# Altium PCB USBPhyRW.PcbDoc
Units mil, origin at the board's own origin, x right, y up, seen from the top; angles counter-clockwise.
Board outline 2170 x 955 mil, 2 copper layers (Top Layer, Bottom Layer); 39 components, 26 nets, 143 pads, 48 vias.
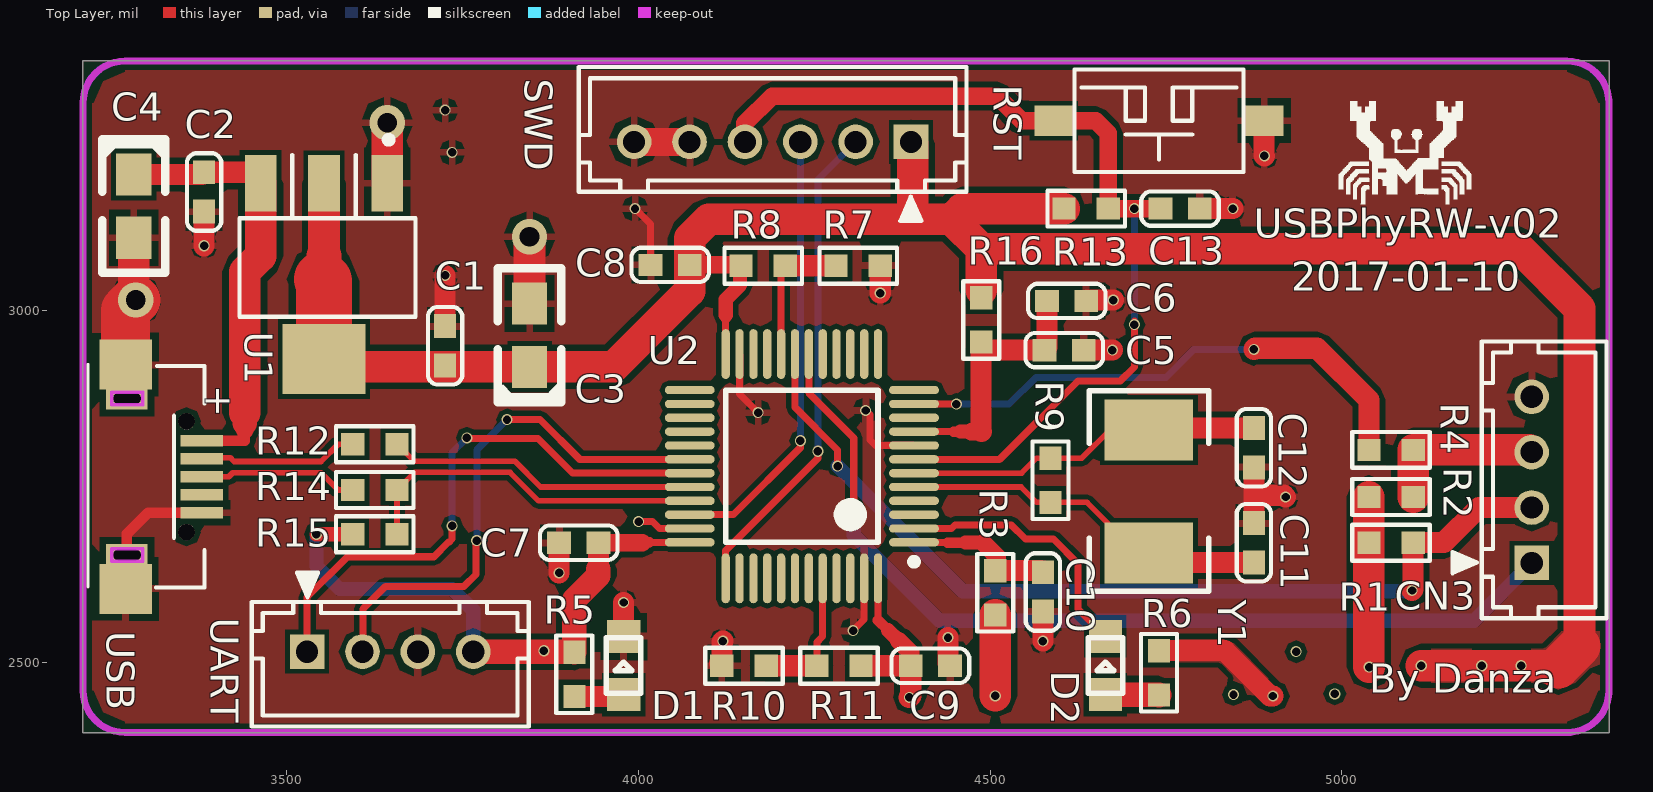
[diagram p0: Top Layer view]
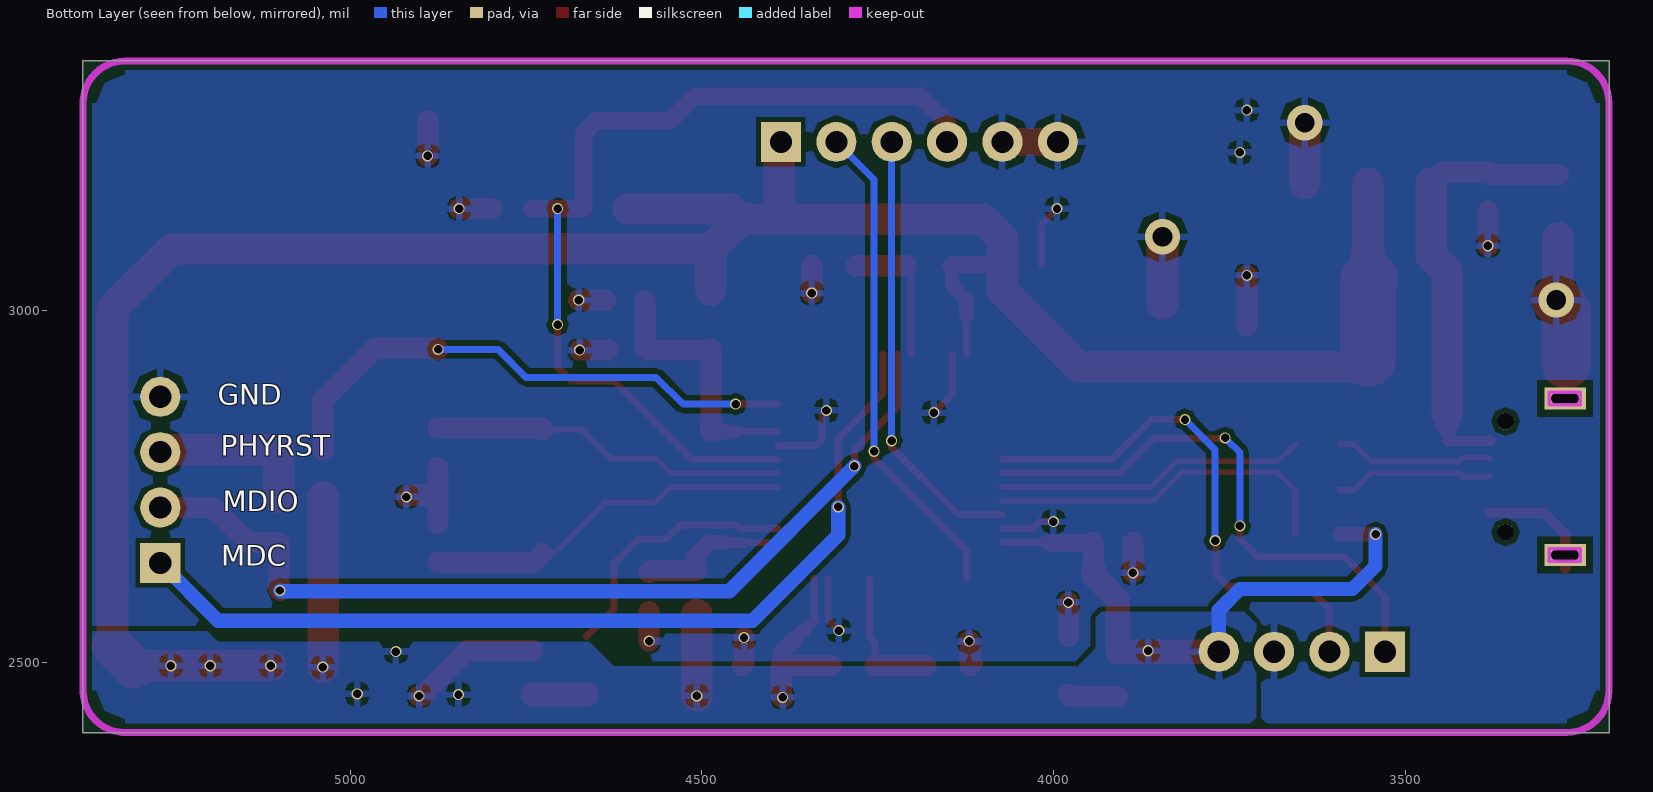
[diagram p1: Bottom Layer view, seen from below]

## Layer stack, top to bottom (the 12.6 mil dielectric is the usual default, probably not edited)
Top Solder: solder mask 0.4, Solder Resist, Dk 3.5
Top Layer: signal copper 1.4
Dielectric 1: dielectric 12.6, FR-4, Dk 4.8
Bottom Layer: signal copper 1.4
Bottom Solder: solder mask 0.4, Solder Resist, Dk 3.5

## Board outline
4045,3355 5380,3355 5380,2420 5380,2410 5380,2400 3210,2400 3210,3345 3210,3355

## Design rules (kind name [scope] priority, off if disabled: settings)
Clearance [All] p1: gap=7
ComponentClearance [All] p1: gap=3 collisioncheckmode=3 verticalgap=7 showdistances=FALSE
DiffPairsRouting [All] p1: maxlimit=8 minlimit=8 mostfreqgap=8 toplayer_minwidth=8 toplayer_maxwidth=30 toplayer_prefwidth=15 bottomlayer_minwidth=8 bottomlayer_maxwidth=30 bottomlayer_prefwidth=15 maxuncoupledlength=500
PolygonConnect [All] p1: connectstyle=Relief reliefconductorwidth=10 reliefentries=4 polygonreliefangle="90 Angle" airgapwidth=10
RoutingVias [All] p1: holewidth=28 width=50 viastyle="Through Hole" minholewidth=10 minwidth=10 maxholewidth=100 maxwidth=100
SilkToSilkClearance [All] p1 off: silktosilkclearance=10
SolderMaskExpansion [All] p1: expansion=4
Width [All] p1: maxlimit=100 minlimit=8 preferedwidth=10 minimp=50.000000 maximp=50.000000 favimp=50.000000
27 further rules are at their usual default settings.

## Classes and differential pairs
component class CoreBoard: C1 C2 C3 C4 C5 C6 C7 C8 C9 C10 C11 C12 C13 CN3 D1 D2 R1 R2 R3 R4 R5 R6 R7 R9 R10 R12 R13 R14 r16 RST SWD U1 UART USB Y1
differential pair USB_1: +NetR12_2 -NetR14_2
differential pair USB_2: +DM_PA11 -DP_PA12
differential pair CLK8M: +OSC_OUT -OSC_IN

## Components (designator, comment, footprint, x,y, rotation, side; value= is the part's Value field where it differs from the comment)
C1 "0.1uf" C0603 3725,2950 r90 top
C2 "0.1uf" C0603 3382.24,3168.74 r270 top
C3 "10uf" SMD-CT-2012 3845,2920 r90 top
C4 "10uf" SMD-CT-2012 3282.24,3193.74 r270 top
C5 "1uf" C0603 4605.2,2943.74 r0 top
C6 "0.1uf" C0603 4608.74,3013.74 r0 top
C7 "0.1uf" C0603 3915,2670 r180 top
C8 "0.1uf" C0603 4045,3065 r180 top
C9 "0.1uf" C0603 4415,2495 r0 top
C10 "0.1uf" C0603 4575,2600 r270 top
C11 "20pF" C0603 4875,2670 r90 top
C12 "20pF" C0603 4875,2805 r90 top
C13 "0.1uf" C0603 4770,3145 r180 top
CN3 "CN_UART" CON_SIP4BOX_2MM 5271.97,2641.26 r90 top
D1 "LED-GREEN" LED-0805 3978.74,2492.76 r270 top
D2 "LED-GREEN" LED-0805 4663.74,2492.76 r270 top
R1 "1.5K/NC" R0603 5070,2670 r180 top
R2 "50k/NC" R0603 5070,2735 r0 top
R3 "0R" R0603 4507.24,2598.74 r270 top
R4 "0R" R0603 5070,2802 r0 top
R5 "1K" R0603 3908.74,2482.76 r270 top
R6 "1K" R0603 4740,2485 r270 top
R7 "10K" R0603 4312.24,3063.82 r180 top
R8 "10K/NC" R0603 4177.24,3063.82 r180 top
R9 "1M" R0603 4585.75,2758.74 r270 top
R10 "10K" R0603 4150,2495 r0 top
R11 "10K/NC" R0603 4285,2495 r0 top
R12 "20R" R0603 3625,2810 r180 top
R13 "10K" R0603 4636.5,3145 r180 top
R14 "20R" R0603 3625,2745 r180 top
R15 "4K7" R0603 3625,2682 r0 top
R16 "0R" R0603 4487.24,2986.74 r270 top (schematic designator L1)
RST "KEYPAD" SWITCH_T06B 4740,3270 r180 top (schematic designator SW1)
SWD "DNP" CON_SIP6BOX_2MM 4387.48,3241.97 r180 top
U1 "LM1117-3.3V" SOT-223 3560,3060 r180 top
U2 "STM32F101C8T6" LQFP48_N 4232.24,2778.74 r180 top
UART "CN_UART" CON_SIP4BOX_2MM 3528.78,2513.03 r0 top (schematic designator CN1)
USB "MICROUSB" MICRO-USB 3292.24,2763.74 r270 top
Y1 "8M" 5032-2P 4725.75,2743.74 r270 top

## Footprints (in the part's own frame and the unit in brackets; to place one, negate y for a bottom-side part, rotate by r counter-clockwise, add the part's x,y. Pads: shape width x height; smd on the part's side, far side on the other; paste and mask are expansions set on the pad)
5032-2P [mm]
  rect 2.2x3.2 smd: 1(-2.2,0) 2(2.25,0)
  silkscreen extent -3.62,-2.16 3.62,2.16
C0603 [mm]
  rect 0.86x0.8 smd: 1(-0.71,0) 2(0.71,0)
  silkscreen extent -1.4,-0.62 1.4,0.62
CON_SIP4BOX_2MM [mm]
  rect 1.25x1.25 / inner rect 1.25x1.25 / far side rect 1.45x1.45 hole 0.8: 1(0,0.05)
  round 1.25 / inner round 1.25 / far side round 1.45 hole 0.8: 2(2,0.05) 3(4,0.05) 4(6,0.05)
  silkscreen extent -2,-2.65 8,2.91
CON_SIP6BOX_2MM [mm]
  rect 1.25x1.25 / inner rect 1.25x1.25 / far side rect 1.45x1.45 hole 0.8: 1(0,0.05)
  round 1.25 / inner round 1.25 / far side round 1.45 hole 0.8: 2(2,0.05) 3(4,0.05) 4(6,0.05) 5(8,0.05) 6(10,0.05)
  silkscreen extent -2,-2.65 12,2.91
LED-0805 [mm]
  rect 1.2x1.2 smd: 1(-1.116,0.003) 2(0.984,0.003)
  silkscreen extent -1.07,-0.62 0.93,0.63
LQFP48_N [mm]
  oval 1.8x0.3 smd: 1(-4.05,2.75) 2(-4.05,2.25) 3(-4.05,1.75) 4(-4.05,1.25) 5(-4.05,0.75) 6(-4.05,0.25) 7(-4.05,-0.25) 8(-4.05,-0.75) 9(-4.05,-1.25) 10(-4.05,-1.75) 11(-4.05,-2.25) 12(-4.05,-2.75) 25(4.05,-2.75) 26(4.05,-2.25) 27(4.05,-1.75) 28(4.05,-1.25) 29(4.05,-0.75) 30(4.05,-0.25) 31(4.05,0.25) 32(4.05,0.75) 33(4.05,1.25) 34(4.05,1.75) 35(4.05,2.25) 36(4.05,2.75)
  oval 0.3x1.8 smd: 13(-2.75,-4.05) 14(-2.25,-4.05) 15(-1.75,-4.05) 16(-1.25,-4.05) 17(-0.75,-4.05) 18(-0.25,-4.05) 19(0.25,-4.05) 20(0.75,-4.05) 21(1.25,-4.05) 22(1.75,-4.05) 23(2.25,-4.05) 24(2.75,-4.05) 37(2.75,4.05) 38(2.25,4.05) 39(1.75,4.05) 40(1.25,4.05) 41(0.75,4.05) 42(0.25,4.05) 43(-0.25,4.05) 44(-0.75,4.05) 45(-1.25,4.05) 46(-1.75,4.05) 47(-2.25,4.05) 48(-2.75,4.05)
  silkscreen extent -4.18,-2.75 2.75,3.57
MICRO-USB [mm]
  rect 0.4x1.55 smd: 1(-1.3,2.2) 2(-0.65,2.2) 3(0,2.2) 4(0.65,2.2) 5(1.3,2.2)
  rect 1.8x1.9 smd: 6(-4.05,-0.55) 6(4.05,-0.55)
  rect 0.8x1.5 hole 0.4 slot 1 at 90 deg: 6(-2.825,-0.5) 6(2.825,-0.5)
  round 0.6 hole 0.6 unplated: ""(-2,1.65) ""(2,1.65)
  Keep-Out Layer lines w0.127: 3.054,-1.043 2.596,-1.043 2.596,0.075 3.054,0.075 3.054,-1.043 ; -2.596,-1.043 -3.054,-1.043 -3.054,0.075 -2.596,0.075 -2.596,-1.043
  silkscreen extent -4.06,-1.91 4,2.3
R0603 [mm]
  rect 0.84x0.8 smd: 1(-0.8,0) 2(0.8,0)
  silkscreen extent -1.4,-0.65 1.4,0.65
SMD-CT-2012 [mil]
  rect 60x50 smd: 1(0,0) 2(90,0)
  silkscreen extent -50,-45 140,45
SOT-223 [mil]
  rect 45x80 smd: 1(-82.76,-121.26) 2(7.24,-121.26) 3(97.24,-121.26)
  rect 118x100 smd: 4(7.24,128.74)
  silkscreen extent -123,-188 127,69
SWITCH_T06B [mm]
  rect 1.4x1.1 smd: 1(-3.8,0) 2(3.8,0)
  silkscreen extent -3.05,-1.85 3.05,1.85

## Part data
C1 C2 C5 C6 C7 C8 C9 C10 C13: library part CAP_1, "Capacitor"
C3 C4: library part CAPACITOR, "Capacitor"
C11 C12: library part CAP, "Capacitor"
CN3 UART: library part CON4
D1 D2: library part LED
R1 R2 R3 R4 R5 R6 R7 R8 R9 R10 R11 R12 R13 R14: library part RES1
R16: library part INDUCTOR1
RST: library part PUSHBUTTON_TSKB-2L_0
SWD: library part CON6
U1: library part LM1117
U2: "STM32 ARM-based 32-bit MCU with 64 Kbytes Flash, 48-pin LQFP, Industrial Temperature"
Y1: library part CRYSTAL, "Crystal"

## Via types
v1: diameter 15.75, hole 12, Top Layer to Bottom Layer, 45 vias
v2: diameter 50, hole 28, Top Layer to Bottom Layer, 3 vias

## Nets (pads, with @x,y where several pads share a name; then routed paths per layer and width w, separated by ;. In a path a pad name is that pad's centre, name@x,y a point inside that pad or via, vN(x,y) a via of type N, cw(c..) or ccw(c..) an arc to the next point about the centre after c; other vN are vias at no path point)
BOOT0: R10.2 R11.1 U2.44 | length 199.7
  Top Layer w10: R11.1 4253.5,2528.5 4261.77,2536.77 U2.44
  Top Layer w30: R10.2 R11.1
BOOT1: R7.2 R8.1 U2.20 | length 200.1
  Top Layer w10: U2.20 4202.72,3057.8 R8.1
  Top Layer w30: R8.1 R7.2
DM_PA11: R12.1 U2.32 | length 441.5
  Top Layer w8: R12.1 3680.5,2786 3824,2786 3860.79,2749.21 U2.32
DP_PA12: R14.1 R15.2 U2.33 | length 506.4
  Top Layer w8: R15.2 R14.1 3681.5,2770 3817.37,2770 3857.84,2729.53 U2.33
GND: C1.2 C2.2 C3.2 C4.2 C5.2 C6.2 C7.2 C8.2 C9.2 C10.2 C11.2 C12.1 C13.1 CN3.4 D1.1 R7.1 R10.1 RST.1 SWD.5 SWD.6 U1.1 U2.8 U2.23 U2.35 U2.47 UART.3 USB.5 USB.6 | length 1742.8
  Top Layer w10: v1(3995,3145) 4017.05,3122.95 C8.2 ; v1(4000,2700) 4020,2700 4029.84,2690.16 U2.35 ; U2.23 4143.66,2881.34 v1(4170,2855) ; v1(4305,2545) 4320.83,2560.83 U2.47 ; v1(4323,2858) 4329,2852 4329,2816 4336.73,2808.27 U2.8
  Top Layer w15: USB.6@3272.56,2633.52 3272.56,2652.52 3272.56,2682.56 3302.56,2712.56 USB.5
  Top Layer w30: v1(3382.24,3092.24) C2.2 ; C1.2 v1(3725,3050) ; v1(3887.05,2627.05) C7.2 ; D1.1 v1(3978.86,2585) ; R10.1@4115,2498.5 R10.1 4118.5,2528.5 v1(4120,2530) ; v1(4343.74,3025) R7.1 ; v1(4440,2535) 4440,2497.95 C9.2 ; v1(4575,2530) C10.2 ; C5.2 v1(4673.74,2943.74) ; C6.2 4637.95,3015 v1(4675,3015) ; C13.1 v1(4845,3145) ; C11.2 4875,2737.5 ; C12.1 4875,2737.5 ; RST.1 4889.61,3220.39 v1(4890,3220) ; v1(4920,2735) 4917.5,2737.5 4875,2737.5
  Top Layer w40: SWD.6 SWD.5
  Top Layer w45: C4.2 3282.24,3017.76 v2(3285,3015) ; U1.1 v2(3642.76,3267.24) ; C3.2 v2(3845,3105)
  Top Layer w70: USB.6@3270.59,2923.19 3270.59,3000.59 v2(3285,3015)
  other v1: 3735,3225 3725,3285
NetD1_2: D1.2 R5.2 | length 71.3
  Top Layer w30: R5.2 3976.1,2451.26 D1.2
NetD2_2: D2.2 R6.2 | length 76.4
  Top Layer w35: D2.2 4739.49,2454.02 R6.2
NetQ1_1: 
NetR12_2: R12.2 USB.2 | length 227.8
  Top Layer w8: USB.2 3380.53,2791 3419.5,2791 3425,2785.5 3548.47,2785.5 3572.97,2810 R12.2
NetR14_2: R14.2 USB.3 | length 229
  Top Layer w8: USB.3@3380.12,2765 USB.3 3417.24,2763.74 3423,2769.5 3548.47,2769.5 3572.97,2745 R14.2
NRST: C13.2 R13.1 RST.2 SWD.4 U2.7 | length 1359.8
  Top Layer w10: U2.7 4513.58,2788.58 4625,2900 4685,2900 4705,2920 v1(4705,2980) v1@4705,2985
  Top Layer w25: SWD.4 4151.26,3266.26 4190,3305 4510,3305 4545,3270 RST.2 4650,3270 4667.99,3252.01 R13.1 v1(4705.02,3145) C13.2
  Bottom Layer w10: v1(4705,2980) v1(4705.02,3145)
OSC_IN: C11.1 R9.2 U2.5 Y1.2 | length 527.7
  Top Layer w8: U2.5 4544.03,2749.21 4566,2727.24 R9.2 4637.76,2727.24 4709.84,2655.16 Y1.2
  Top Layer w30: Y1.2 4738.86,2642.05 C11.1
OSC_OUT: C12.2 R9.1 U2.6 Y1.1 | length 509.8
  Top Layer w8: U2.6 4544.66,2768.9 4566,2790.24 R9.1 4630.24,2790.24 4670.35,2830.35 Y1.1
  Top Layer w30: Y1.1 4728.35,2832.95 C12.2
PC13: D2.1 U2.2 | length 377.5
  Top Layer w10: U2.2 4445.16,2690.16 4450,2695 4530,2695 4550,2675 4590,2675 4625,2640 4625,2575.55 D2.1
PHYRST: R4.1 U2.11 | length 781.5
  Top Layer w10: U2.11 v1@4452.32,2867.32
  Top Layer w30: v1(4875,2945) 4876.5,2946.5 4965,2946.5 5038.5,2872.99 R4.1
  Bottom Layer w10: v1(4452,2867) 4527,2867 4565,2905 4750,2905 4790,2945 v1(4875,2945)
PHYRST#: CN3.3 R2.2 R4.2 | length 241.5
  Top Layer w45: R2.2 R4.2 ; R4.2@5104.76,2798.74 R4.2 ; CN3.3 5266.74,2802 R4.2
RX1: U2.31 UART.1 | length 808.3
  Top Layer w10: UART.1 3528.78,2592.78 3586,2650 3709,2650 3730,2671 3731,2671 3735,2675 v1(3735,2694) ; v1(3756,2819) 3757,2818 3857,2818 3906.1,2768.9 U2.31
  Bottom Layer w10: v1(3735,2694) 3735,2798 v1(3756,2819)
SMIMDC: CN3.1 U2.18 | length 1332.3
  Top Layer w10: U2.18 4242.09,2882.91 4306,2819 v1(4306,2721)
  Bottom Layer w20: v1(4306,2721) 4306,2681 4428,2559 5187.74,2559 CN3.1
SMIMDIO: CN3.2 R1.1 U2.19 | length 1333.3
  Top Layer w10: U2.19 4222.4,2862.6 4283,2802 v1(4283,2779)
  Top Layer w30: v1(5100,2602) 5101.5,2603.5 R1.1 5145,2670 5195,2720 CN3.2
  Bottom Layer w20: v1(4283,2779) 4461,2601 5099,2601 v1(5100,2602)
SWCLK: SWD.2 U2.37 | length 697.2
  Top Layer w10: U2.37 4123.98,2658.98 4255,2790 v1(4255,2800)
  Bottom Layer w10: v1(4255,2800) 4255,3186.26 SWD.2
SWDIO: SWD.3 U2.34 | length 631.6
  Top Layer w10: U2.34 4134.84,2709.84 4230,2805 v1(4230,2815)
  Bottom Layer w10: v1(4230,2815) SWD.3
TX1: U2.30 UART.2 | length 763.9
  Top Layer w10: UART.2 3608,2515.48 3608,2576 3640,2608 3752,2608 3769,2625 3769,2672 v1(3770,2673) ; v1(3813,2845) 3860,2845 3916.42,2788.58 U2.30
  Bottom Layer w10: v1(3770,2673) 3770,2802 v1(3813,2845)
USB_5V: C2.1 C4.1 U1.3 USB.1 | length 625
  Top Layer w15: USB.1 3439.92,2814.92 3439.92,2829.92
  Top Layer w25: 3439.92,2829.92 3439.92,2839.92
  Top Layer w30: C4.1 3379.29,3193.74 C2.1 3447.32,3196.69 U1.3
  Top Layer w35: 3439.92,2839.92 3439.92,2854.92
  Top Layer w45: 3439.92,2854.92 3439.92,2909.92 3440,2910 3440,3055 3462.76,3077.76 U1.3
VBAT: C10.1 R3.1 U2.1 | length 216.4
  Top Layer w10: U2.1 4392.17,2670 4440,2670
  Top Layer w15: 4440,2670 4465,2670
  Top Layer w20: 4465,2670 4490,2670
  Top Layer w25: 4490,2670 4510,2650 4507.24,2647.24 R3.1
  Top Layer w30: R3.1 4572.72,2630.24 C10.1
VCC_3V3: C1.1 C3.1 C7.1 C8.1 C9.1 R1.2 R2.1 R3.2 R5.1 R6.1 R8.2 R11.2 R13.2 R15.1 R16.1 SWD.1 U1.2 U1.4 U2.24 U2.36 U2.48 UART.4 | length 5143.4
  Top Layer w10: 4015.47,2670.47 U2.36 ; U2.24 4123.98,2988.98 ; 4340.51,2560 U2.48
  Top Layer w15: 4005.47,2670.47 4015.47,2670.47 ; 4123.98,2988.98 4123.98,2993.98 ; 4340.51,2560 4355,2545.51
  Top Layer w20: v1(3542,2682) R15.1 ; 4005,2670 4005.47,2670.47 ; 4123.98,2993.98 4123.98,3015.98 4144.57,3036.57 R8.2@4144.57,3065 ; 4355,2545.51 4370,2530.51
  Top Layer w25: C7.1 4005,2670 ; C8.1 4144.57,3065 R8.2 ; 4370,2530.51 4387.05,2513.46 C9.1
  Top Layer w30: 3942.95,2632.05 C7.1 ; R11.2 C9.1 4387.05,2452.05 v1(4385,2450) ; R6.1 4833.5,2516.5 4898,2452 v1(4902,2452)
  Top Layer w35: UART.4 3907.99,2515 R5.1 3908.74,2588.74 3942.95,2622.95 3942.95,2632.05
  Top Layer w45: U1.4 3564.02,2920 C3.1 3965,2920 4072.95,3027.95 C8.1 4072.95,3102.95 4100,3130 4390,3130 ; 3552.76,3077.76 U1.2 ; SWD.1 4390,3237.48 4390,3130 ; R16.1@4487.24,3028.74 4487.24,3087.76 ; v1(4507.24,2452.24) R3.2 ; R13.2 4460,3145 4445,3130 ; R2.1 R1.2 5038.5,2493.5 v1(5039,2493) ; v1(5113,2495) v1(5199,2495) v1(5255,2495) 5306,2495 5308,2493 ; 5338,2523 5338,3003 5253.24,3087.76 4487.24,3087.76 ; 4390,3130 4445,3130 ; 4445,3130 4487.24,3087.76
  Top Layer w50: 3552.76,3047.24 3552.76,3077.76
  Top Layer w55: 3550,3044.49 3552.76,3047.24
  Top Layer w60: 5308,2493 5338,2523
  Top Layer w80: 3550,3044.49 3552.76,3041.73 U1.4
  Bottom Layer w20: v1(3542,2682) 3542,2637 3575,2604 3735,2604 3765,2574 UART.4
  other v1: 4846,2454 4990,2455 4935,2515 3865.4,2516.32
VDDA: C5.1 C6.1 R16.2 U2.9 | length 375.2
  Top Layer w10: U2.9 4447.95,2827.95
  Top Layer w15: 4447.95,2827.95 4457.95,2827.95
  Top Layer w20: 4457.95,2827.95 4472.95,2827.95
  Top Layer w25: 4472.95,2827.95 4487.95,2827.95
  Top Layer w30: 4487.95,2827.95 4487.24,2828.66 4487.24,2944.74 4488.24,2943.74 C5.1 4580.79,2947.28 C6.1
pads on no net: U2.3 U2.4 U2.10 U2.12 U2.13 U2.14 U2.15 U2.16 U2.17 U2.21 U2.22 U2.25 U2.26 U2.27 U2.28 U2.29 U2.38 U2.39 U2.40 U2.41 U2.42 U2.43 U2.45 U2.46 USB. USB.4

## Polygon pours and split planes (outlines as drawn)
VCC_3V3 on Top Layer "VCC_3V3_L01_P018" (solid, remove dead copper, pour order 18): 4739.33,2540.03 4739,2539.7 4739,2413 5333,2413 5368,2448 5368,2544 4743.69,2544 4740,2540.31
VCC_3V3 on Top Layer "VCC_3V3_L01_P016" (solid, remove dead copper, pour order 16): 4901,2539 4904,2542 5321,2542 5359,2542 5367,2534 5368,2533 5368,2448 5366,2448 5331,2413 5327,2409 5139,2409 4903,2409 4901,2411
GND on Top Layer "GND_L01_P010" (solid, remove dead copper, pour order 10): 3210,3355 3210,2400 5380,2400 5380,2406 5380,3355 5224,3355 3210,3355
GND on Bottom Layer "GND_L02_P014" (solid, remove dead copper, pour order 14): 5381,2400 5381,3354 5380,3355 3210,3355 3210,2400 5381,2400
VCC_3V3 on Bottom Layer "VCC_3V3_L02_P012" (solid, remove dead copper, pour order 12): 5375,2544 5203,2544 5188,2529 4962,2529 4660,2529 4628,2497 4625,2494 4518,2494 3968,2494 3967,2493 3940,2520 3940,2532 3940,2563 3939,2564 3931,2572 3780,2572 3729,2572 3718,2561 3712,2555 3712,2468 3712,2421 3730,2403 3731,2402 4616,2402 5374,2402

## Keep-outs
Keep-Out Layer:
  lines w10: 5320,2400 ccw(c5320,2460) 5380,2460 ; 5325,2400 3285,2400 3270,2400 cw(c3270,2460) 3210,2460 3210,2475 3210,3295 cw(c3270,3295) 3270,3355 5320,3355 cw(c5320,3295) 5380,3295 ; 5380,2455 5380,3300

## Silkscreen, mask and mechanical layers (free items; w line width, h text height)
Top Overlay:
  drawing of 673 lines, arcs and shapes, not listed
  text "USBPhyRW-v02" at 4875,3090 h70
  text "2017-01-10" at 4928,3015 h70
  text "By Danza" at 5039,2443 h70
Bottom Overlay:
  text "GND" at 5188,2856 h50
  text "PHYRST" at 5184,2784 h50
  text "MDIO" at 5181,2705 h50
  text "MDC" at 5183,2627 h50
